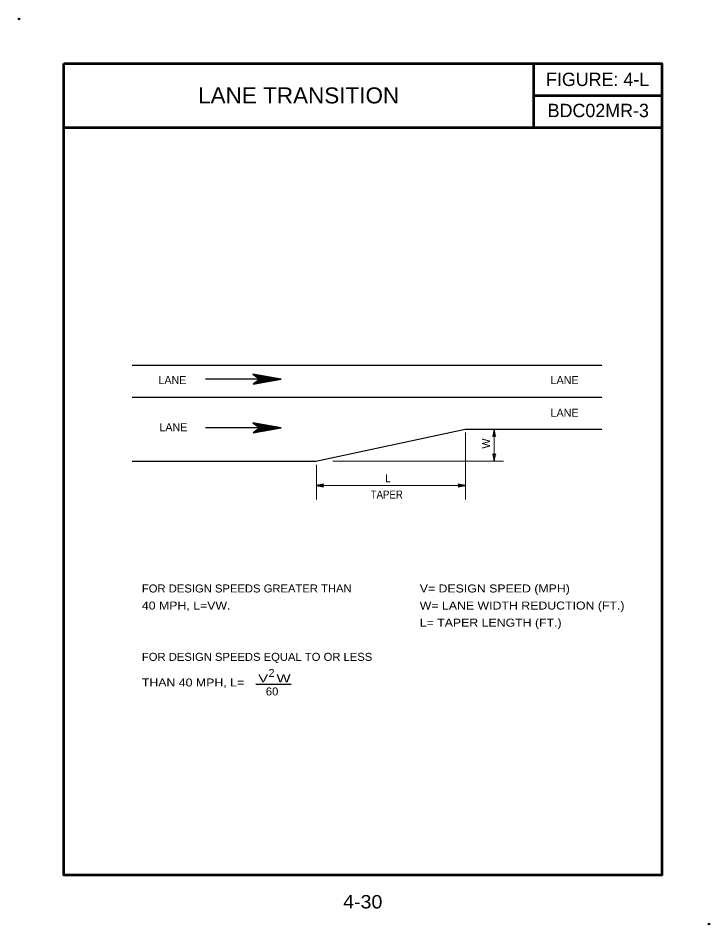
# Model space of a CAD drawing. Extents: x -2.652 to -1.977, y 1.265 to 2.149.
import ezdxf
from ezdxf.enums import TextEntityAlignment as Align

# ---------------------------------------------------------------- set-up
doc = ezdxf.new("R2010")
doc.units = 0
doc.header["$LTSCALE"] = 0.0031
doc.header["$PDMODE"] = 32
doc.header["$PDSIZE"] = 0.00155
doc.layers.add('1', color=7, linetype='Continuous', lineweight=25)
doc.layers.add('24', color=7, linetype='Continuous', lineweight=25)

msp = doc.modelspace()

# ---------------------------------------------------------------- linework, layer by layer
at = {"layer": '1', "lineweight": 53}
for p, q in [((-2.14865, 2.105133), (-2.14865, 2.042633)), ((-2.14865, 2.073883), (-2.02365, 2.073883)), ((-2.606983, 2.042633), (-2.02365, 2.042633))]:
    msp.add_line(p, q, dxfattribs=at)
at = {"layer": '1'}
for p, q in [((-2.540317, 1.810867), (-2.081983, 1.810867)), ((-2.394733, 1.79725), (-2.468575, 1.797283)), ((-2.540317, 1.779617), (-2.081983, 1.779617)), ((-2.39475, 1.749775), (-2.468575, 1.7498)), ((-2.215317, 1.748367), (-2.081983, 1.748367)), ((-2.419675, 1.499675), (-2.385208, 1.499675))]:
    msp.add_line(p, q, dxfattribs=at)
at = {"layer": '1', "lineweight": 13}
for p, q in [((-2.215142, 1.745125), (-2.21515, 1.679808)), ((-2.187042, 1.748217), (-2.187042, 1.717375)), ((-2.344483, 1.717117), (-2.177817, 1.717117)), ((-2.36045, 1.713633), (-2.360458, 1.679842)), ((-2.360458, 1.693583), (-2.215325, 1.693583))]:
    msp.add_line(p, q, dxfattribs=at)
at = {"layer": '1', "lineweight": 53}
msp.add_lwpolyline([(-2.606983, 2.105133), (-2.02365, 2.105133), (-2.02365, 1.313467), (-2.606983, 1.313467)], close=True, dxfattribs=at)
at = {"layer": '1'}
msp.add_lwpolyline([(-2.540317, 1.717117), (-2.36115, 1.717117), (-2.215317, 1.748367)], dxfattribs=at)
for p in [(-2.650742, 2.148433), (-1.977408, 1.265933)]:
    msp.add_point(p, dxfattribs=at)
at = {"layer": '24'}
for points in [[(-2.394733, 1.79725), (-2.42245, 1.802167), (-2.415833, 1.797258), (-2.422308, 1.792442), (-2.394733, 1.79725), (-2.396575, 1.7972), (-2.421675, 1.8018), (-2.415317, 1.7972), (-2.421192, 1.792817), (-2.397567, 1.797117), (-2.398492, 1.79725), (-2.419992, 1.801083), (-2.415167, 1.7972), (-2.420133, 1.793442), (-2.398917, 1.797258), (-2.399833, 1.797117), (-2.418625, 1.800517), (-2.414975, 1.797258), (-2.418708, 1.793883), (-2.402508, 1.797117), (-2.404075, 1.797117), (-2.417233, 1.799817), (-2.414675, 1.797342), (-2.417433, 1.794583), (-2.40435, 1.797258), (-2.405833, 1.797342), (-2.415733, 1.799042), (-2.413825, 1.797117), (-2.415892, 1.795225), (-2.407192, 1.797258), (-2.408592, 1.7974), (-2.414533, 1.798533), (-2.41355, 1.7972), (-2.415175, 1.795717), (-2.409317, 1.797258), (-2.413192, 1.798183), (-2.412633, 1.797125), (-2.414333, 1.796058), (-2.410292, 1.797117), (-2.412833, 1.797758), (-2.411767, 1.796917), (-2.412992, 1.796417), (-2.411775, 1.7972), (-2.412408, 1.797342)], [(-2.39475, 1.749775), (-2.422467, 1.754683), (-2.41585, 1.749783), (-2.422325, 1.744958), (-2.39475, 1.749775), (-2.396592, 1.749725), (-2.421692, 1.754317), (-2.415333, 1.749725), (-2.421208, 1.745342), (-2.397583, 1.749642), (-2.398508, 1.749775), (-2.420008, 1.753608), (-2.415183, 1.749725), (-2.42015, 1.745967), (-2.398933, 1.749783), (-2.39985, 1.749642), (-2.418642, 1.753042), (-2.414992, 1.749783), (-2.418725, 1.7464), (-2.402525, 1.749642), (-2.404092, 1.749642), (-2.41725, 1.752342), (-2.414692, 1.749858), (-2.41745, 1.747108), (-2.404367, 1.749775), (-2.40585, 1.749867), (-2.41575, 1.751558), (-2.413842, 1.749642), (-2.415908, 1.747742), (-2.407208, 1.749783), (-2.408608, 1.749917), (-2.41455, 1.751058), (-2.413567, 1.749725), (-2.415192, 1.748242), (-2.409333, 1.749783), (-2.413208, 1.750708), (-2.41265, 1.749642), (-2.41435, 1.748583), (-2.410308, 1.749642), (-2.41285, 1.750275), (-2.411783, 1.749442), (-2.413008, 1.748942), (-2.411792, 1.749717), (-2.412425, 1.749858)], [(-2.187042, 1.748217), (-2.188267, 1.741283), (-2.187042, 1.742942), (-2.185833, 1.741325), (-2.187042, 1.748217), (-2.187033, 1.747758), (-2.188175, 1.741483), (-2.187025, 1.743075), (-2.185933, 1.7416), (-2.187008, 1.747508), (-2.187042, 1.747275), (-2.188, 1.7419), (-2.187025, 1.743108), (-2.186083, 1.741867), (-2.187042, 1.747175), (-2.187008, 1.746942), (-2.187858, 1.742242), (-2.187042, 1.743158), (-2.1862, 1.742225), (-2.187008, 1.746275), (-2.187008, 1.745883), (-2.187683, 1.742592), (-2.187058, 1.743233), (-2.186375, 1.742542), (-2.187042, 1.745808), (-2.187067, 1.745442), (-2.187483, 1.742967), (-2.187008, 1.743442), (-2.186533, 1.742925), (-2.187042, 1.7451), (-2.187075, 1.74475), (-2.187358, 1.743267), (-2.187025, 1.743508), (-2.186658, 1.743108), (-2.187042, 1.744575), (-2.187275, 1.7436), (-2.187008, 1.743742), (-2.186742, 1.743317), (-2.187008, 1.744325), (-2.187167, 1.743692), (-2.186958, 1.743958), (-2.186833, 1.74365), (-2.187025, 1.743958), (-2.187058, 1.7438)], [(-2.187042, 1.717375), (-2.185817, 1.724308), (-2.187042, 1.72265), (-2.18825, 1.724267), (-2.187042, 1.717375), (-2.187058, 1.717833), (-2.185908, 1.724108), (-2.187058, 1.722517), (-2.18815, 1.723992), (-2.187075, 1.718083), (-2.187042, 1.718317), (-2.186083, 1.723692), (-2.187058, 1.722483), (-2.188, 1.723725), (-2.187042, 1.718417), (-2.187075, 1.71865), (-2.186225, 1.72335), (-2.187042, 1.722433), (-2.187883, 1.723367), (-2.187075, 1.719317), (-2.187075, 1.719708), (-2.1864, 1.723), (-2.187025, 1.722358), (-2.187708, 1.72305), (-2.187042, 1.719783), (-2.187017, 1.72015), (-2.1866, 1.722625), (-2.187075, 1.72215), (-2.18755, 1.722667), (-2.187042, 1.720492), (-2.187008, 1.720842), (-2.186725, 1.722325), (-2.187058, 1.722083), (-2.187425, 1.722483), (-2.187042, 1.721017), (-2.186808, 1.721992), (-2.187075, 1.72185), (-2.187342, 1.722275), (-2.187075, 1.721267), (-2.186917, 1.7219), (-2.187125, 1.721633), (-2.18725, 1.721942), (-2.187058, 1.721633), (-2.187025, 1.721792)], [(-2.360458, 1.693583), (-2.353525, 1.692358), (-2.355183, 1.693583), (-2.353567, 1.694792), (-2.360458, 1.693583), (-2.36, 1.6936), (-2.353725, 1.69245), (-2.355317, 1.6936), (-2.353842, 1.694692), (-2.35975, 1.693617), (-2.359517, 1.693583), (-2.354142, 1.692625), (-2.35535, 1.6936), (-2.354108, 1.694542), (-2.359417, 1.693583), (-2.359183, 1.693617), (-2.354483, 1.692767), (-2.3554, 1.693583), (-2.354467, 1.694425), (-2.358517, 1.693617), (-2.358125, 1.693617), (-2.354833, 1.692942), (-2.355475, 1.693567), (-2.354783, 1.69425), (-2.35805, 1.693583), (-2.357683, 1.693558), (-2.355208, 1.693142), (-2.355683, 1.693617), (-2.355167, 1.694092), (-2.357342, 1.693583), (-2.356992, 1.69355), (-2.355508, 1.693267), (-2.35575, 1.6936), (-2.35535, 1.693967), (-2.356817, 1.693583), (-2.355842, 1.69335), (-2.355983, 1.693617), (-2.355558, 1.693883), (-2.356567, 1.693617), (-2.355933, 1.693458), (-2.3562, 1.693667), (-2.355892, 1.693792), (-2.3562, 1.6936), (-2.356042, 1.693567)], [(-2.215325, 1.693583), (-2.222258, 1.694808), (-2.2206, 1.693583), (-2.222217, 1.692375), (-2.215325, 1.693583), (-2.215783, 1.693575), (-2.222058, 1.694717), (-2.220467, 1.693567), (-2.221942, 1.692475), (-2.216033, 1.69355), (-2.216267, 1.693583), (-2.221642, 1.694542), (-2.220433, 1.693567), (-2.221675, 1.692625), (-2.216367, 1.693583), (-2.2166, 1.69355), (-2.2213, 1.6944), (-2.220383, 1.693583), (-2.221317, 1.692742), (-2.217267, 1.69355), (-2.217658, 1.69355), (-2.22095, 1.694225), (-2.220308, 1.6936), (-2.221, 1.692917), (-2.217733, 1.693583), (-2.2181, 1.693608), (-2.220575, 1.694025), (-2.2201, 1.69355), (-2.220617, 1.693075), (-2.218442, 1.693583), (-2.218792, 1.693617), (-2.220275, 1.6939), (-2.220033, 1.693567), (-2.220433, 1.6932), (-2.218967, 1.693583), (-2.219942, 1.693817), (-2.2198, 1.69355), (-2.220225, 1.693283), (-2.219217, 1.69355), (-2.21985, 1.693708), (-2.219583, 1.6935), (-2.219892, 1.693375), (-2.219583, 1.693567), (-2.219742, 1.6936)]]:
    msp.add_lwpolyline(points, dxfattribs=at)

# ---------------------------------------------------------------- texts
at = {"layer": '1'}
for s, height, p in [('FIGURE: 4-L', 0.01303, (-2.086146, 2.082992)), ('BDC02MR-3', 0.01303, (-2.085504, 2.052658)), ('LANE', 0.007808, (-2.500975, 1.792433)), ('LANE', 0.007808, (-2.118392, 1.792433)), ('LANE', 0.007808, (-2.118392, 1.76055)), ('LANE', 0.007808, (-2.500042, 1.746475))]:
    msp.add_text(s, height=height, dxfattribs=at).set_placement(p, align=Align.CENTER)
for s, height, width, p in [('LANE TRANSITION', 0.01562, 1.05, (-2.377813, 2.066067)), ('L', 0.007808, 0.9, (-2.290821, 1.696767)), ('TAPER', 0.007808, 0.9, (-2.291892, 1.680825)), ('4-30', 0.01303, 1.1, (-2.315317, 1.281167))]:
    msp.add_text(s, height=height, dxfattribs=dict(at, width=width)).set_placement(p, align=Align.CENTER)
msp.add_text('W', height=0.007808, rotation=90, dxfattribs=at).set_placement((-2.191033, 1.734408), align=Align.CENTER)
for s, width, p in [('FOR DESIGN SPEEDS GREATER THAN', 1.05, (-2.530783, 1.589233)), ('V= DESIGN SPEED (MPH)', 1.15, (-2.2597, 1.589233)), ('40 MPH, L=VW.', 1.15, (-2.530783, 1.572567)), ('W= LANE WIDTH REDUCTION (FT.)', 1.15, (-2.2597, 1.572567)), ('L= TAPER LENGTH (FT.)', 1.15, (-2.2597, 1.5559)), ('FOR DESIGN SPEEDS EQUAL TO OR LESS', 1.05, (-2.530783, 1.522567)), ('THAN 40 MPH, L=', 1.15, (-2.530783, 1.497567)), ('V  W', 1.4, (-2.417317, 1.50165)), ('60', 1.05, (-2.409858, 1.488858))]:
    msp.add_text(s, height=0.007808, dxfattribs=dict(at, width=width)).set_placement(p)
msp.add_text('2', height=0.007808, dxfattribs=at).set_placement((-2.407175, 1.506875))

doc.saveas('drawing.dxf')
